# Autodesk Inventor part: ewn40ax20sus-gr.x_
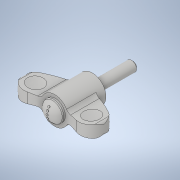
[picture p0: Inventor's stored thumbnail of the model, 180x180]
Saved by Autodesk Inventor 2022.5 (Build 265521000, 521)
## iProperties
Created: 2021-08
Part Number: ewn40ax20sus-gr.x_
Material: 一般
Document SubType Name: Modeling
Designer: ImaoCorp
Density: 1 g/cm^3
Appearance: 既定
Sending System: SOLIDWORKS 2019-2019304
MC: AMD64
MC_MODEL: Intel64 Family 6 Model 60 Stepping 3, GenuineIntel
OS: Windows_NT
FRU: Parasolid Version 31.0, build 290,  9- 1-2019
FORMAT: text
GUISE: transmit
KEY: ewn40ax20sus-gr
FILE: ewn40ax20sus-gr.x_t
DATE: Wed Aug 11 15:03:09 2021
Author: ImaoCorp
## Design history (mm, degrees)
feature "Base1"
node "ソリッド1"
